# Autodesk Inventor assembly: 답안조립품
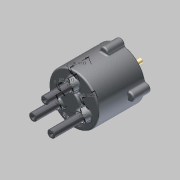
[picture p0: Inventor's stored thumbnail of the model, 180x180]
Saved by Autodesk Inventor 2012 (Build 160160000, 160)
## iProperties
Created: 2014-12
Part Number: 답안조립품
Document SubType Name: Assembly
Designer: HOME
Author: HOME
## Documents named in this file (14)
- C:\Users\HOME\Desktop\Inventor1급\답안조립품.iam
- C:\Users\HOME\Desktop\Inventor1급\몸체.ipt
- C:\Users\HOME\Desktop\Inventor1급\커버.ipt
- C:\Users\HOME\Desktop\Inventor1급\M5x0.5x20.ipt
- C:\Users\HOME\Desktop\Inventor1급\베어링 NA 4900.ipt
- C:\Users\HOME\Desktop\Inventor1급\오일실.ipt
- C:\Users\HOME\Desktop\Inventor1급\메인 축.ipt
- C:\Users\HOME\Desktop\Inventor1급\멈춤링 10 x 1.ipt
- C:\Users\HOME\Desktop\Inventor1급\멈춤링 22 x 1.2.ipt
- C:\Users\HOME\Desktop\Inventor1급\판캠.ipt
- C:\Users\HOME\Desktop\Inventor1급\슬라이드 축.ipt
- C:\Users\HOME\Desktop\Inventor1급\11.가변스프링.ipt
- C:\Users\HOME\Desktop\Inventor1급\12.가변스프링.ipt
- C:\Users\HOME\Desktop\Inventor1급\13.가변스프링.ipt
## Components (7 placed, 4 different names)
1. 11.가변스프링:1
2. 12.가변스프링:1
3. 13.가변스프링:1
4. M5x0.5x20:1 — 각도:1
5. M5x0.5x20:2
6. M5x0.5x20:3
7. M5x0.5x20:4
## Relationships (1: Angle 1)
- 각도:1 [Angle]: M5x0.5x20:1
